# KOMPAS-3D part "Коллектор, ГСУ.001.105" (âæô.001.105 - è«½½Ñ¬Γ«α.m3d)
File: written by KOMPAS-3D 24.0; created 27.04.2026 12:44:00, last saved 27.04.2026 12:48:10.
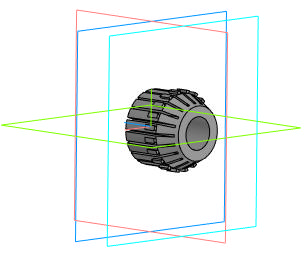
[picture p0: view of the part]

Document properties: Автор: User7; Полное имя файла: C:\Users\User7\Desktop\олимп\ГСУ.001.105 - Коллектор.m3d

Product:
- Part/product: Коллектор  | designation ГСУ.001.105
    Масса: 0.0199

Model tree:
1. Эскиз:1
2. Элемент вращения:1
     Угол 1 = 360
3. Смещенная плоскость:1
     Расстояние = 10.5
4. Эскиз:2  (with: Грань.Элемент вращения:1)
5. Элемент выдавливания:1
     Расстояние 2 = 15.5
6. Эскиз:3  (with: Ребро.Элемент вращения:1)
7. Элемент выдавливания:2
     Расстояние 2 = 3
8. Массив по концентрической сетке:1  (with: Элемент выдавливания:2, Смещенная плоскость:1, Эскиз:3, Элемент выдавливания:1, Эскиз:2, Грань.Элемент вращения:1)  (20 pattern instances)
     Шаг 2 = 360

Expressions: 19.4/2
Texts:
  ГСУ.001.105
